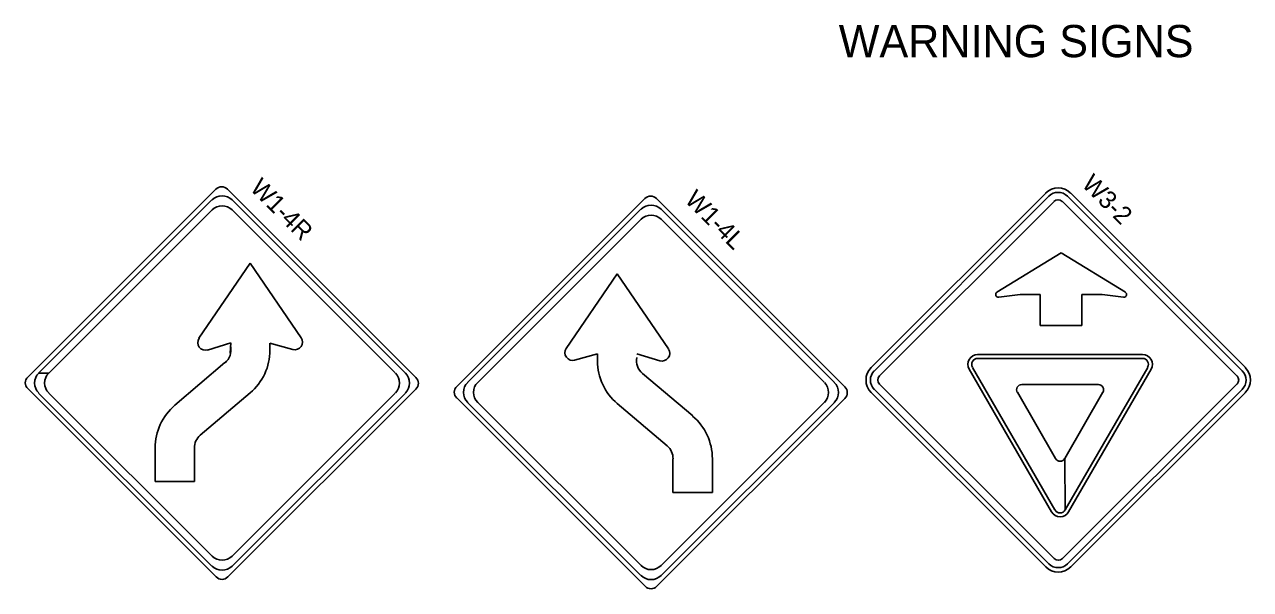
# Model space of a CAD drawing. Extents: x 1531.44 to 1538.58, y 1529.59 to 1539.3.
# Drawn here: x 1531.443 to 1535.547, y 1537.403 to 1539.297 of the extents above; entities that cross this region are included whole.
import ezdxf

# ---------------------------------------------------------------- set-up
doc = ezdxf.new("R2010")
doc.units = 0
for name, color, linetype in [('DETL-LINE', 7, 'Continuous'), ('DETL-NOTE', 7, 'Continuous'), ('DETL-TITL', 7, 'Continuous')]:
    doc.layers.add(name, color=color, linetype=linetype)

msp = doc.modelspace()

# ---------------------------------------------------------------- linework, layer by layer
at = {"layer": 'DETL-LINE'}
for p, q in [((1531.4542, 1538.1152), (1532.0837, 1538.7447)), ((1532.1226, 1538.7447), (1532.7536, 1538.114)), ((1531.4907, 1538.1284), (1532.0709, 1538.709)), ((1532.1381, 1538.709), (1532.7183, 1538.1284)), ((1532.8901, 1538.0838), (1533.5196, 1538.7133)), ((1533.5584, 1538.7133), (1534.1895, 1538.0826)), ((1534.8618, 1538.7309), (1534.2775, 1538.1466)), ((1534.8724, 1538.7212), (1534.2881, 1538.136)), ((1534.3048, 1538.1193), (1534.89, 1538.7036)), ((1534.9168, 1538.7036), (1534.9173, 1538.7036)), ((1535.5016, 1538.1193), (1534.9173, 1538.7036)), ((1534.9173, 1538.7036), (1535.5016, 1538.1193)), ((1534.9173, 1538.7036), (1535.5016, 1538.1193)), ((1535.5192, 1538.136), (1534.9349, 1538.7212)), ((1535.5298, 1538.1466), (1534.9454, 1538.7309)), ((1532.0713, 1538.6752), (1531.5245, 1538.1284)), ((1532.0712, 1538.6752), (1532.0713, 1538.6752)), ((1532.6845, 1538.1288), (1532.1381, 1538.6752)), ((1533.5068, 1538.6776), (1532.9266, 1538.097)), ((1534.1542, 1538.097), (1533.574, 1538.6776)), ((1532.9604, 1538.097), (1533.5072, 1538.6438)), ((1533.574, 1538.6438), (1534.1204, 1538.0974)), ((1532.199, 1538.4968), (1532.0274, 1538.2452)), ((1532.3697, 1538.2469), (1532.199, 1538.4968)), ((1534.9129, 1538.5312), (1534.6982, 1538.3992)), ((1535.1285, 1538.3992), (1534.9129, 1538.5312)), ((1533.2567, 1538.2108), (1533.4274, 1538.4608)), ((1533.4274, 1538.4608), (1533.599, 1538.2091)), ((1534.7043, 1538.3824), (1534.7756, 1538.3912)), ((1534.7756, 1538.3912), (1534.8425, 1538.3912)), ((1534.8425, 1538.3912), (1534.8425, 1538.2874)), ((1534.9824, 1538.2874), (1534.9824, 1538.3912)), ((1534.9824, 1538.3912), (1535.051, 1538.3912)), ((1535.051, 1538.3912), (1535.1223, 1538.3824)), ((1535.1281, 1538.399), (1535.1285, 1538.3992)), ((1532.3696, 1538.247), (1532.3697, 1538.2469)), ((1534.8425, 1538.2874), (1534.9824, 1538.2874)), ((1532.0564, 1538.2056), (1532.1338, 1538.2293)), ((1532.1338, 1538.2293), (1532.1321, 1538.195)), ((1532.265, 1538.2047), (1532.265, 1538.2284)), ((1532.265, 1538.2284), (1532.3415, 1538.2073)), ((1533.3614, 1538.1924), (1533.2849, 1538.1712)), ((1533.3614, 1538.1695), (1533.3614, 1538.1924)), ((1533.57, 1538.1695), (1533.4926, 1538.1932)), ((1533.5699, 1538.1698), (1533.57, 1538.1695)), ((1534.9094, 1538.1906), (1534.6339, 1538.1906)), ((1534.6339, 1538.1774), (1534.9094, 1538.1774)), ((1534.9094, 1538.1906), (1535.1857, 1538.1906)), ((1534.9094, 1538.1774), (1535.1857, 1538.1774)), ((1531.5245, 1538.1284), (1531.4907, 1538.1284)), ((1532.1145, 1538.1633), (1531.9464, 1538.0208)), ((1533.5119, 1538.1272), (1533.68, 1537.9847)), ((1534.8812, 1537.6635), (1534.6049, 1538.1413)), ((1534.8926, 1537.6696), (1534.6163, 1538.1475)), ((1535.2033, 1538.1475), (1534.927, 1537.6696)), ((1535.2147, 1538.1413), (1534.9384, 1537.6635)), ((1532.9604, 1538.0972), (1532.9604, 1538.097)), ((1534.89, 1537.5068), (1534.3048, 1538.0912)), ((1534.9094, 1538.0903), (1534.7818, 1538.0903)), ((1535.0378, 1538.0903), (1534.9094, 1538.0903)), ((1535.5016, 1538.0912), (1534.9173, 1537.5068)), ((1532.0853, 1537.4453), (1531.4542, 1538.0764)), ((1532.0709, 1537.4814), (1531.4907, 1538.0616)), ((1531.5245, 1538.0616), (1532.0713, 1537.5152)), ((1532.0318, 1537.9204), (1532.199, 1538.0621)), ((1532.7536, 1538.0748), (1532.1241, 1537.4453)), ((1532.7183, 1538.0616), (1532.1381, 1537.4814)), ((1532.1381, 1537.5152), (1532.6845, 1538.0616)), ((1533.5212, 1537.4139), (1532.8901, 1538.045)), ((1534.1895, 1538.0434), (1533.56, 1537.4139)), ((1534.2775, 1538.063), (1534.8618, 1537.4787)), ((1534.2881, 1538.0736), (1534.8724, 1537.4892)), ((1534.7668, 1538.0639), (1534.8944, 1537.8421)), ((1534.9252, 1537.8421), (1535.0528, 1538.0639)), ((1534.9349, 1537.4892), (1535.5192, 1538.0736)), ((1534.9454, 1537.4787), (1535.5298, 1538.063)), ((1532.9266, 1538.0302), (1533.5068, 1537.45)), ((1533.5072, 1537.4838), (1532.9604, 1538.0302)), ((1533.5946, 1537.8844), (1533.4274, 1538.026)), ((1533.574, 1537.45), (1534.1542, 1538.0302)), ((1534.1204, 1538.0302), (1533.574, 1537.4838)), ((1531.8804, 1537.8773), (1531.8804, 1537.7647)), ((1532.0124, 1537.7647), (1532.0124, 1537.8773)), ((1533.614, 1537.7286), (1533.614, 1537.8412)), ((1533.746, 1537.8412), (1533.746, 1537.7286)), ((1534.9252, 1537.8421), (1534.927, 1537.6696)), ((1534.927, 1537.6696), (1534.9252, 1537.8421)), ((1531.8804, 1537.7647), (1532.0124, 1537.7647)), ((1533.746, 1537.7286), (1533.614, 1537.7286))]:
    msp.add_line(p, q, dxfattribs=at)
for centre, radius, start, end in [((1534.9029, 1538.6897), 0.059, 45, 135), ((1534.9029, 1538.6897), 0.0443, 45, 135), ((1534.9029, 1538.6897), 0.0197, 45, 135), ((1534.7029, 1538.3916), 0.00876, 121.5745, 276.9405), ((1535.1235, 1538.3916), 0.00876, 263.0849, 58.4254), ((1532.3482, 1538.2324), 0.0258, 254.5104, 34.2603), ((1532.0491, 1538.2305), 0.0258, 145.7397, 286.8976), ((1532.0782, 1538.2058), 0.0563, 310.3349, 10.7451), ((1533.2782, 1538.1965), 0.0258, 145.7397, 285.4896), ((1533.5774, 1538.1945), 0.0258, 253.1025, 34.2603), ((1532.0772, 1538.205), 0.1878, 310.3349, 0), ((1533.5492, 1538.1691), 0.1878, 180, 229.6651), ((1533.5482, 1538.1699), 0.0563, 169.2549, 229.6651), ((1534.6337, 1538.1578), 0.0329, 90, 210), ((1534.6337, 1538.1578), 0.0197, 90, 210), ((1535.1858, 1538.1578), 0.0329, 330, 90), ((1535.1858, 1538.1578), 0.0197, 330, 90), ((1534.3191, 1538.1051), 0.059, 135, 225), ((1534.3191, 1538.1051), 0.0443, 135, 225), ((1535.488, 1538.1051), 0.0443, 315, 45), ((1535.488, 1538.1051), 0.059, 315, 45), ((1534.3191, 1538.1051), 0.0197, 135, 225), ((1534.7817, 1538.0723), 0.0175, 90, 210), ((1535.0379, 1538.0723), 0.0175, 330, 90), ((1535.488, 1538.1051), 0.0197, 315, 45), ((1532.0684, 1537.8772), 0.1878, 130.3349, 180), ((1533.5581, 1537.8413), 0.1878, 0, 49.6652), ((1532.0684, 1537.8772), 0.0563, 130.3348, 180), ((1533.5581, 1537.8413), 0.0563, 0, 49.6652), ((1534.9098, 1537.8505), 0.0175, 210, 330), ((1534.9098, 1537.6796), 0.0329, 210, 330), ((1534.9098, 1537.6796), 0.0197, 210, 330), ((1534.9035, 1537.5207), 0.059, 225, 315), ((1534.9035, 1537.5207), 0.0443, 225, 315), ((1534.9035, 1537.5207), 0.0197, 225, 315)]:
    msp.add_arc(centre, radius, start, end, dxfattribs=at)
for centre, major_axis, start_param, end_param in [((1532.1033, 1538.7251), (-0.0276, 0), 3.926991, 5.497787), ((1532.1046, 1538.6752), (-0.0473, 0), 3.926991, 5.497787), ((1533.5391, 1538.6937), (-0.0276, 0), 3.926991, 5.497787), ((1532.1047, 1538.6417), (-0.0473, 0), 3.926991, 5.497787), ((1533.5405, 1538.6438), (-0.0473, 0), 3.926991, 5.497787), ((1533.5406, 1538.6103), (-0.0473, 0), 3.926991, 5.497787), ((1531.5245, 1538.0951), (-0.0473, 0), 5.497787, 7.068584), ((1531.558, 1538.0951), (-0.0473, 0), 5.497787, 7.068584), ((1532.6513, 1538.0951), (-0.0473, 0), 2.356195, 3.926991), ((1532.6848, 1538.0951), (-0.0473, 0), 2.356195, 3.926991), ((1531.4738, 1538.0957), (-0.0276, 0), 5.497787, 7.068584), ((1532.7341, 1538.0943), (-0.0276, 0), 2.356195, 3.926991), ((1532.9097, 1538.0643), (-0.0276, 0), 5.497787, 7.068584), ((1532.9604, 1538.0637), (-0.0473, 0), 5.497787, 7.068584), ((1532.9939, 1538.0637), (-0.0473, 0), 5.497787, 7.068584), ((1534.0872, 1538.0637), (-0.0473, 0), 2.356195, 3.926991), ((1534.1206, 1538.0637), (-0.0473, 0), 2.356195, 3.926991), ((1534.17, 1538.0629), (-0.0276, 0), 2.356195, 3.926991), ((1532.1047, 1537.5485), (-0.0473, 0), 0.785398, 2.356194), ((1532.1046, 1537.515), (-0.0473, 0), 0.785398, 2.356194), ((1533.5405, 1537.5171), (-0.0473, 0), 0.785398, 2.356194), ((1532.1047, 1537.4648), (-0.0276, 0), 0.785398, 2.356194), ((1533.5405, 1537.4836), (-0.0473, 0), 0.785398, 2.356194), ((1533.5405, 1537.4334), (-0.0276, 0), 0.785398, 2.356194)]:
    msp.add_ellipse(centre, major_axis=major_axis, ratio=0.999977, start_param=start_param, end_param=end_param, dxfattribs=at)

# ---------------------------------------------------------------- texts
at = {"layer": 'DETL-NOTE'}
for s, p in [('W1-4R', (1532.1953, 1538.7445)), ('W3-2', (1534.979, 1538.7576)), ('W1-4L', (1533.6505, 1538.705))]:
    msp.add_text(s, height=0.06, rotation=315, dxfattribs=at).set_placement(p)
at = {"layer": 'DETL-TITL'}
msp.add_text('WARNING SIGNS', height=0.108, dxfattribs=at).set_placement((1534.1688, 1539.1869))

doc.saveas('drawing.dxf')
